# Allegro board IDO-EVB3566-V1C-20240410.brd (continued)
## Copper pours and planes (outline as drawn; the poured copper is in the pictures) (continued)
VBAT_WL_1T1R on TOP: 83.57,48.18 83.57,46.23 83.69,46.1 84.2,46.1 84.2,47.62 84.84,48.26 86.61,48.26 87.99,49.63 88.21,49.63 88.37,49.78 88.37,50.47 88.32,50.52 87.63,50.52 86.26,49.15 84.33,49.15 83.86,48.68 83.86,48.48
VCC2V8_DVP on BOTTOM: 53.31,7.37 52.12,7.37 51.97,7.21 51.97,4.65 51.99,4.62 51.99,3.51 52.7,2.79 54.99,2.79 55.12,2.92 55.12,3.81 54.99,3.94 54.23,3.94 53.37,4.8 53.37,7.32
VCC2V8_DVP on BOTTOM: 78.87,4.32 78.23,4.32 77.98,4.06 77.22,4.06 76.71,3.56 76.71,2.16 76.83,2.03 78.26,2.03 78.36,2.13 78.36,3 78.44,3.07 78.89,3.07 78.99,3.17 78.99,4.19
VCC2V8_DVP on L3_S2: 70.46,4.22 71.96,5.71 75.06,5.71 75.44,5.33 75.44,2.54 75.69,2.29 77.6,2.29 77.98,2.67 77.98,4.45 75.56,6.86 69.34,6.86 69.02,6.54 67.3,6.54 66.42,5.66 55.45,5.66 53.98,4.19 53.98,3.56 54.1,3.43 56.26,3.43 57.66,4.83 60.58,4.83 61.19,4.22
VCC3V3_SYS on TOP: 41.1,20.83 41.1,19.71 42.21,18.59 45.19,18.59 45.67,19.08 47.5,19.08 47.57,19 48.41,19 49.43,20.02 49.43,32.49 49.5,32.56 61.77,32.56 61.93,32.72 61.93,33.25 61.47,33.71 49.81,33.71 49.45,33.35 49.17,33.35 48.67,32.84 48.67,32.54 48.01,31.88 48.01,20.73 47.35,20.07 42.49,20.07 42.37,20.19 42.37,20.95 42.24,21.08 41.35,21.08
VCC3V3_SYS on TOP: 14.05,16.41 16.92,16.41 17.14,16.64 17.14,17.5 17.37,17.73 18.01,17.73 18.54,18.26 19.23,18.26 19.66,18.69 19.66,20.45 19.46,20.65 16.81,20.65 16.51,20.35 14,20.35 13.84,20.19 13.84,16.61
VCC3V3_SYS on TOP: 86.82,47.73 88.24,47.73 88.37,47.85 88.37,48.97 88.34,49 87.53,49 87.53,48.72 87.1,48.29 87,48.29 86.82,48.11
VCC3V3_SYS on BOTTOM: 68.55,19.86 68.38,20.04 68.38,20.32 68.35,20.35 63.98,20.35 63.73,20.6 63.73,32.44 63.65,32.51 61.21,32.51 60.93,32.79 60.93,33.38 61.26,33.71 61.48,33.71 61.59,33.59 64.55,33.59 64.85,33.3 64.85,21.64 65.41,21.08 67.34,21.08 67.69,21.44 67.69,22.12 67.74,22.17 69.27,22.17 69.29,22.15 69.29,21.79 70.92,21.79 77.42,28.3 77.83,28.3 78.08,28.55 78.08,28.96 78.44,29.31 78.44,29.54 79.17,30.28 79.17,31.04 80.54,32.41 81.2,32.41 81.61,32 81.61,31.72 80.64,30.76 80.64,29.03 78.91,27.29 78.57,27.29 78.33,27.05 78.33,26.72 71.96,20.35 69.01,20.35 69.01,20.09 68.78,19.86
VCC3V3_SYS on BOTTOM: 45.06,7.7 44.75,7.39 44.75,6.78 44.7,6.73 43.99,6.73 43.94,6.78 43.94,9.17 43.99,9.22 44.68,9.22 45.06,8.84
VCC3V3_SYS on BOTTOM: 86.56,47.85 86.56,40.54 86.77,40.34 87.55,40.34 87.73,40.51 87.73,47.5 87.96,47.73 87.96,48.16 87.78,48.34 87.05,48.34
VCC3V3_SYS on L3_S2: 80.39,32.18 80.39,32.16 80.26,32.03 80.26,31.83 80.75,31.34 88.34,31.34 89.09,32.09 89.89,32.09 90.06,32.26 90.7,32.26 92.2,33.76 92.2,36.6 87.86,40.94 86.69,40.94 86.56,40.82 86.56,40.46 91.16,35.86 91.16,34.37 91.03,34.24 91.03,34.06 90.61,33.64 90.44,33.64 89.97,33.17 88.57,33.17 87.78,32.38 80.59,32.38
VCC3V3_SYS on L3_S2: 21.23,13.41 20.87,13.78 19.37,13.78 16.36,16.79 16.36,17.48 16.28,17.55 16.28,18.75 16.41,18.87 17.42,18.87 17.58,18.72 17.58,17.09 19.51,15.16 20.88,15.16 21.49,14.55 25.76,14.55 26.64,15.44 28.45,15.44 28.83,15.06 34.26,15.06 34.52,14.81 36.42,14.81 36.68,15.06 36.75,15.06 39.93,18.24 39.93,19.84 41.35,21.26 42.19,21.26 42.34,21.11 42.34,20.52 42.16,20.35 41.88,20.35 41.05,19.51 41.05,17.78 37.2,13.93 36.08,13.93 35.69,13.54 26.49,13.54 26.37,13.41
VCC5V0_USB_FE_D1 on BOTTOM: 90.42,18.54 93.85,18.54 95.38,20.07 97.28,20.07 97.41,20.19 97.41,21.34 97.28,21.46 94.61,21.46 93.09,19.94 90.3,19.94 90.17,19.81 90.17,18.8
VCC5V0_USB_FE_D1 on L3_S2: 103,23.75 100.08,23.75 98.17,21.84 96.65,21.84 96.39,21.59 96.39,19.94 96.65,19.68 98.93,19.68 100.97,21.72 103,21.72 103.12,21.84 103.12,23.62
VCC5V0_USB_FE_D2 on BOTTOM: 97.41,34.54 95.89,34.54 95,35.43 91.87,35.43 90.96,34.52 90.96,34.06 90.3,33.4 90.3,32.38 90.35,32.33 91.77,32.33 91.82,32.38 91.82,32.77 91.95,32.89 93.47,32.89 93.98,32.38 97.41,32.38 97.54,32.51 97.54,34.42
VCC5V0_USB_FE_D3 on BOTTOM: 90.5,24.38 95.89,24.38 96.27,24 97.26,24 97.54,23.72 97.54,22.33 96.88,21.67 95.45,21.67 93.8,23.32 92.02,23.32 91.82,23.52 90.6,23.52 90.4,23.72 90.4,24.28
VCC5V0_USB_FE_D4 on BOTTOM: 94.61,15.24 92.13,15.24 91.59,14.71 90.6,14.71 90.3,14.4 90.3,13.72 90.42,13.59 95,13.59 95.25,13.84 95.25,14.61
VCC5V0_USB_FE_D4 on L3_S2: 95.63,15.37 94.36,15.37 94.11,15.11 94.11,14.1 94.82,13.39 94.82,10.85 95.63,10.03 101.68,10.03 103.23,11.58 103.23,12.85 102.84,13.23 101.6,13.23 101.37,13 101.37,12.73 100.08,11.43 96.14,11.43 95.94,11.63 95.94,15.06
VCC5V0_USB_HOST1 on TOP: 46.61,57.4 45.97,57.4 45.85,57.53 45.85,60.07 46.23,60.45 47.5,60.45 47.75,60.2 47.75,59.69 47.5,59.44 46.99,59.44 46.74,59.18 46.74,57.53
VCC5V0_USB_HOST1 on BOTTOM: 56.01,61.59 46.35,61.59 46.1,61.34 46.1,59.69 46.35,59.44 52.93,59.44 53.14,59.64 53.52,59.64 53.72,59.44 55.75,59.44 56.26,59.94 56.26,61.34
VCC5V0_USB_HOST2 on BOTTOM: 90.55,28.32 94.74,28.32 95.12,27.94 95.12,26.92 94.87,26.67 94.23,26.67 93.73,27.18 92.2,27.18 91.82,27.56 90.55,27.56 90.42,27.69 90.42,28.19
VCC5V0_USB_HOST2 on L3_S2: 100.84,34.42 98.81,32.38 96.6,32.38 93.98,29.77 93.98,26.92 94.49,26.42 95.38,26.42 96.52,27.56 97.87,27.56 103.15,32.84 103.15,34.34 103.07,34.42
VCC5V0_USB_OTG on TOP: 64.39,55.88 64.52,55.75 66.42,55.75 66.55,55.88 66.55,60.2 66.42,60.33 64.64,60.33 64.39,60.07
VCC5V0_USB_OTG on TOP: 72.26,56.9 74.3,56.9 74.42,57.02 74.42,58.93 74.3,59.05 72.26,59.05 72.14,58.93 72.14,57.02
VCC5V0_USB_OTG on BOTTOM: 74.68,57.02 74.68,59.05 74.17,59.56 67.69,59.56 66.93,60.33 65.41,60.33 65.28,60.2 65.28,56.64 66.04,55.88 72.14,55.88 73.15,56.9 74.55,56.9
VCC5V_SYS on TOP: 53.72,43.94 53.72,36.2 54.1,35.81 58.17,35.81 58.78,36.42 58.78,44.07 58.65,44.2 53.98,44.2
VCC5V_SYS on TOP: 73.91,48.64 71.53,48.64 71.37,48.79 71.37,50.42 71.53,50.57 73.86,50.57 74.04,50.39 74.04,48.77
VCC5V_SYS on TOP: 11.76,28.4 19.99,28.4 20.07,28.32 20.07,25.4 19.56,24.89 15.88,24.89 15.75,25.02 15.75,26.04 15.11,26.67 11.68,26.67 11.56,26.8 11.56,28.19
VCC5V_SYS on BOTTOM: 72.8,48.13 73.36,48.13 73.38,48.16 73.38,48.9 74.14,49.66 74.14,54.69 74.13,54.7 73.19,54.7 72.57,54.08 72.57,54.03 71.37,52.83 71.37,51.94 71.2,51.77 71.2,49.15 71.53,48.82 72.59,48.82 72.77,48.64 72.77,48.16
VCC5V_SYS on L3_S2: 62.81,46.61 55.75,46.61 55.24,46.1 55.24,43.56 55.37,43.43 60.33,43.43 60.77,43.88 67.37,43.88 67.56,44.07 70.74,44.07 73.41,46.74 73.41,49.91 72.26,51.05 67.26,51.05
VCC5V_SYS on L3_S2: 18.44,25.27 23.11,25.27 26.16,28.32 30.73,28.32 35.31,32.89 63.37,32.89 64.26,33.78 64.26,35.56 64.11,35.71 62.94,35.71 61.57,37.08 45.62,37.08 45.44,36.91 33.6,36.91 29.72,33.02 23.37,33.02 17.75,27.41 17.75,25.96
VCC-AMP on TOP: 85.98,30.1 82.55,30.1 82.42,29.97 82.42,26.29 82.55,26.16 85.9,26.16 86.11,26.37 86.11,26.67 86.03,26.75 84.28,26.75 84.23,26.8 84.23,28.85 84.12,28.96 84.12,29.36 84.23,29.46 85.98,29.46 86.11,29.59 86.11,29.97
VCC-AMP on BOTTOM: 83.79,31.5 82.93,31.5 82.68,31.24 82.68,26.21 82.8,26.09 82.8,25.37 82.91,25.27 83.62,25.27 84.28,25.93 84.28,28.83 84.12,28.98 84.12,30.12 83.87,30.38 83.87,31.42
VCC_3V3_HUB on TOP: 84.73,16.23 84.66,16.15 84.66,15.27 84.71,15.21 85.19,15.21 85.78,14.63 88.37,14.63 88.39,14.66 88.39,15.44 88.37,15.47 87.38,15.47 86.61,16.23
VCC_3V3_HUB on TOP: 81.97,21.29 81.97,20.45 81.84,20.32 81.13,20.32 80.72,20.73 80.72,21.16 80.87,21.31 81.94,21.31
VCC_3V3_HUB on TOP: 88.01,20.27 89.05,20.27 89.13,20.19 89.13,18.77 88.93,18.57 88.01,18.57 87.96,18.62 87.96,20.22
VCC_3V3_HUB on TOP: 85.29,19.81 85.47,19.63 86.33,19.63 86.33,19.71 87.6,20.98 87.6,22.28 87.4,22.48 87.4,23.29 87.25,23.44 82.85,23.44 82.83,23.42 82.83,22.89 82.85,22.86 86.16,22.86 86.23,22.78 86.23,21.77 85.29,20.83
VCC_3V3_HUB on BOTTOM: 87.33,20.88 85.93,20.88 84.58,22.23 80.14,22.23 79.5,21.59 79.5,18.92 78.54,17.96 77.19,17.96 77.06,17.83 77.06,16.99 79.07,14.99 85.85,14.99 85.89,15.02 85.89,16.09 85.78,16.21 85.37,16.21 85.17,16 81.41,16 80.77,16.64 80.77,20.09 80.87,20.19 81.41,20.19 81.94,20.73 84.71,20.73 84.86,20.57 84.86,19.91 84.89,19.89 85.27,19.89 85.65,19.51 89.03,19.51 89.15,19.63 89.15,19.91 89,20.07 88.14,20.07
VCC_5V on TOP: 4.6,48.29 4.6,50.62 1.4,50.62 1.4,48.29
VCC_5V on TOP: 16,38.48 15.49,38.99 11.43,38.99 11.18,38.73 11.18,36.83 11.43,36.58 18.41,36.58 18.8,36.2 20.7,36.2 20.83,36.32 20.83,37.87 20.22,38.48
VCC_5V on TOP: 74.93,56.9 77.47,56.9 77.6,57.02 77.6,59.18 77.34,59.44 75.06,59.44 74.8,59.18 74.8,57.02
VCC_5V on TOP: 5.31,11.66 5.31,14.27 3.51,16.08 1.85,16.08 1.68,16.26 1.68,17.7 2.13,18.16 5.77,18.16 6.38,17.55 6.38,11.84 8.18,10.03 9.35,10.03 9.73,9.65 11.79,9.65 11.84,9.6 11.84,8.97 11.19,8.32 8.65,8.32
VCC_5V on TOP: 77.42,21.26 77.57,21.11 77.98,21.11 78.16,21.29 78.16,21.44 78.31,21.59 78.31,21.97 78.33,22 78.46,22 78.56,22.1 79.1,22.1 79.12,22.12 79.12,22.73 79.04,22.81 78.05,22.81 77.42,22.17
VCC_5V on BOTTOM: 57.78,61.85 60.45,61.85 60.58,61.72 60.58,58.8 60.33,58.55 57.78,58.55 57.53,58.8 57.53,61.59
VCC_5V on BOTTOM: 82.17,26.16 79.86,26.16 79.76,26.06 79.76,24.59 80.77,23.57 82.25,23.57 82.42,23.75 82.42,25.15 82.22,25.35 82.22,26.11
VCC_5V on BOTTOM: 86.11,14.94 86.11,16.26 85.98,16.38 85.98,19.18 86.11,19.3 88.9,19.3 89.03,19.18 89.03,17.78 88.9,17.65 87.63,17.65 87.5,17.53 87.5,16.76 87.76,16.51 88.77,16.51 89.03,16.26 89.03,12.95 88.9,12.83 86.92,12.83 86.87,12.88 86.87,13.49 85.95,14.4 85.95,14.78
VCC_5V on BOTTOM: 88.98,33.02 86.89,33.02 85.88,32 85.88,23.39 86.06,23.22 88.9,23.22 89.05,23.37 89.05,25.04 88.68,25.41 87.69,25.41 87.66,25.45 87.66,26.97 87.81,27.13 89.1,27.13 89.18,27.2 89.18,28.4 89,28.57 87.73,28.57 87.6,28.7 87.6,29.24 87.76,29.39 87.76,31.37 88.01,31.62 88.98,31.62 89.08,31.72 89.08,32.92
VCC_5V on BOTTOM: 44.68,3.25 43.46,3.25 42.57,2.36 39.93,2.36 39.88,2.41 39.88,2.79 39.75,2.92 37.72,2.92 37.21,2.41 34.67,2.41 34.54,2.29 16.26,2.29 13.72,4.83 13.46,4.83 9.91,8.38 9.91,9.65 9.65,9.91 8.38,9.91 8.26,9.78 8.26,6.63 13.74,1.14 45.47,1.14 45.72,1.4 45.72,3.76 45.64,3.84 44.96,3.84 44.88,3.76 44.88,3.45
VCC_5V on L3_S2: outline of 112 points within 1.23,11.84 96.01,65.53
VCC_12V on TOP: 16.43,42.21 16.38,42.16 15.75,42.16 15.57,42.34 13.36,42.34 13.34,42.37 13.34,42.42 12.06,43.69 12.06,51.59 12.61,52.13 16.12,52.13 16.43,51.82 16.43,48.31 15.39,47.27 15.39,43.87 15.47,43.79 15.93,43.79 16,43.71 16,42.82 16.03,42.8 16.13,42.8 16.43,42.49
VCC_12V on TOP: 27.18,7.49 25.53,7.49 25.4,7.37 25.4,5.84 24.77,5.21 24.77,3.94 24.89,3.81 27.69,3.81 27.81,3.94 27.81,5.33 27.3,5.84 27.3,7.37
VCC_12V on TOP: 16.43,34.11 15.88,34.67 11.56,34.67 11.3,34.42 11.3,32.77 11.56,32.51 12.32,32.51 12.95,33.15 14.35,33.15 15.88,31.62 16.71,31.62 16.74,31.65 16.74,32.69 17.27,33.22 17.27,33.76 17.25,33.78 16.48,33.78 16.43,33.83
VCC_12V on TOP: 73.66,7.39 72.44,7.39 72.39,7.34 72.39,4.78 72.64,4.52 73.53,4.52 73.71,4.7 73.71,5.61 73.69,5.64 73.69,7.37
VCC_12V on BOTTOM: 75.44,5.97 70.36,5.97 70.1,5.71 70.1,4.19 70.23,4.06 75.31,4.06 75.56,4.32 75.56,5.84
VCC_12V on BOTTOM: 15.62,52.32 15.62,47.24 15.24,46.86 11.3,46.86 10.16,48.01 10.16,52.22 10.64,52.7 15.24,52.7
VCC_12V on BOTTOM: 23.88,3.81 28.57,3.81 28.73,3.96 28.73,5.69 28.7,5.71 24.18,5.71 23.75,5.28 23.75,3.94
VCC_12V on L3_S2: 8.13,6.35 8.13,2.41 9.4,1.14 74.55,1.14 75.06,1.65 75.06,5.33 74.8,5.59 72.11,5.59 70.56,4.04 61.19,4.04 59.94,2.79 58.17,2.79 57.66,3.3 30.61,3.3 29.91,4 29.91,4.89 29.34,5.46 25.91,5.46 24,3.56 16.64,3.56 14.86,5.33 12.65,5.33 8.99,8.99 8.99,11.1 8.5,11.6 6.77,11.6 6.27,12.09 6.27,20.6 6.81,21.13 6.81,24.74 5.23,26.31 5.23,32.36 5.19,32.4 5.51,32.72 12.57,32.72 12.57,34.29 11.93,34.94 5.73,34.94 5.21,35.46 5.21,40.01 5.56,40.36 6.2,40.36 13.18,47.35 15.37,47.35 15.88,47.85 15.88,48.9 14.58,50.19 11.48,50.19 1.63,40.34 1.63,12.85
VCC_DCIN on BOTTOM: 7.11,65.28 3.05,65.28 1.63,63.86 1.63,59.59 2.67,58.55 6.73,58.55 10.29,54.99 14.61,54.99 14.69,55.08 14.69,57.16 12.57,59.28 10.06,59.28 9.27,60.07 9.27,62.36 7.37,64.26 7.37,65.02
VCC_LEDA_TX1 on TOP: 54.74,7.34 53.92,7.34 53.85,7.26 53.85,5.84 53.47,5.46 53.47,4.7 53.72,4.45 54.48,4.45 54.61,4.57 54.61,5.54 54.79,5.71 54.79,7.29
VCC_LEDA_TX1 on BOTTOM: 31.39,3.53 31.5,3.43 31.5,2.79 31.75,2.54 33.4,2.54 33.53,2.67 33.53,4.7 32.64,5.59 29.08,5.59 28.96,5.46 28.96,3.81 29.24,3.53
VCC_LEDA_TX1 on L3_S2: 32.21,4.62 31.17,5.66 30.43,5.66 30.23,5.46 30.23,4.19 31.01,3.4 45.09,3.4 47.62,5.94 52.35,5.94 53.85,4.45 54.36,4.45 54.61,4.7 54.61,6.22 53.49,7.34 47.47,7.34 44.75,4.62
VCC_LEDK_TX1 on TOP: 50.8,5.97 49.91,5.97 49.91,8.05 49.63,8.33 48.67,8.33 47.8,7.47 47.42,7.47 47.24,7.65 47.24,7.87 48.34,8.97 50.5,8.97 50.8,8.66
VCCIO5_IN on TOP: 24.26,16.64 22.61,16.64 22.48,16.51 22.48,14.86 22.61,14.73 24.26,14.73 24.38,14.86 24.38,16.51
VCCIO5_IN on BOTTOM: 22.61,14.73 22.99,14.73 23.06,14.81 23.06,15.29 23.14,15.37 23.15,15.35 24.63,15.35 24.69,15.42 24.69,16 24.59,16.1 22.53,16.1 22.43,16 22.43,14.91
VDD_3V3 on TOP: 15.37,14.99 15.24,14.86 15.24,12.32 15.06,12.14 13,12.14 12.73,11.86 12.27,11.86 12.19,11.79 12.19,10.69 12.24,10.64 12.52,10.64 12.67,10.79 16.69,10.79 16.76,10.87 16.76,13.18 16.38,13.56 16.38,14.91 16.31,14.99
VDD_3V3 on TOP: 89.46,21.51 89.15,21.51 88.16,22.5 88.16,23.29 88.19,23.32 88.93,23.32 89.69,22.56 89.69,21.74
VDD_3V3 on TOP: 19.2,7.39 18.44,7.39 18.34,7.29 18.34,5.87 18.06,5.59 17.3,5.59 17.28,5.58 16.5,5.58 16.38,5.46 16.38,3.89 16.54,3.73 18.85,3.73 19.3,4.19 19.3,4.83 19.25,4.88 19.25,7.34
VDD_3V3 on TOP: 90.93,5.97 91.67,5.97 91.69,5.99 91.69,7.49 91.77,7.57 93.5,7.57 93.73,7.8 93.73,8.92 93.64,9 93.62,8.99 89.59,8.99 89.56,8.97 89.56,8.28 89.89,7.95 90.45,7.95 90.91,7.49 90.91,5.99
VDD_3V3 on TOP: 36.17,7.39 35.43,7.39 35.36,7.32 35.36,6.02 35.18,5.84 34.52,5.84 34.42,5.74 34.42,4.57 34.54,4.45 36.04,4.45 36.17,4.57 36.17,5.61 36.25,5.69 36.25,7.32
VDD_3V3 on BOTTOM: 17.88,32.28 17.88,32.97 17.73,33.12 16.76,33.12 16.74,33.15 16.74,33.96 16.71,33.99 16.13,33.99 15.75,33.6 15.75,32.56 15.72,32.54 14.17,32.54 14.12,32.49 14.12,32.08 14.15,32.05 16.15,32.05 16.33,32.23 17.83,32.23
VDD_3V3 on BOTTOM: 14.1,25.53 15.88,25.53 16,25.65 16.64,25.65 16.69,25.6 16.69,25.07 16.64,25.02 16.64,24.38 16.51,24.26 15.75,24.26 15.49,24 14.1,24 13.97,24.13 13.97,25.4
VDD_3V3 on BOTTOM: 78.99,5.97 78.87,5.84 78.11,5.84 77.98,5.97 77.98,6.99 77.72,7.24 77.22,7.24 77.09,7.37 77.09,7.87 77.22,8 77.47,8 78.61,9.14 93.6,9.14 93.98,8.76 93.98,6.99 93.73,6.73 91.06,6.73 90.55,7.24 89.61,7.24 89.61,8.05 89.51,8.15 88.75,8.15 88.65,8.05 88.65,5.97 88.52,5.84 87.88,5.84 87.76,5.97 87.76,6.35 87.5,6.6 86.36,6.6 85.85,7.11 84.73,7.11 84.73,8.05 84.71,8.08 83.92,8.08 83.85,8 83.85,7.09 83.74,7.09 83.74,5.89 83.64,5.79 83.13,5.79 82.94,5.98 82.94,7.1 81.79,8.26 79.12,8.26 79.12,7.16 78.99,7.04
VDD_3V3 on BOTTOM: 19.05,3.56 16.51,3.56 16.38,3.68 16.38,5.21 16.51,5.33 19.05,5.33 19.18,5.21 19.18,3.68
VDD_3V3 on BOTTOM: 36.17,5.61 35.08,5.61 34.92,5.46 34.92,4.7 35.18,4.45 36.07,4.45 36.2,4.57 36.2,5.59
VDD_3V3 on L3_S2: outline of 103 points within 9.32,3.81 94.61,33.15
VDD_USB_5V on TOP: 80.44,20.62 80.52,20.7 80.52,21.29 80.63,21.4 80.64,21.4 80.64,21.41 80.75,21.51 82.04,21.51 82.17,21.39 82.17,20.4 82.22,20.35 82.4,20.35 82.47,20.42 82.47,23.34 82.32,23.5 81.48,23.5 81.36,23.37 81.36,22.78 80.92,22.35 79.91,22.35 79.5,21.95 79.5,21.64 79.22,21.36 78.33,21.36 78.28,21.31 78.28,20.65 78.31,20.62
(no net) on TOP: 100.2,69.6 103.76,69.6 104.39,69.34 104.65,68.71 104.65,1.27 104.39,0.64 103.76,0.38 1.27,0.38 0.64,0.64 0.38,1.27 0.38,68.71 0.64,69.34 1.27,69.6 13.97,69.6 14.22,69.34 14.22,56.39 14.33,56.29 14.33,56.26 17.45,53.14 31.83,53.14 34.72,56.03 34.72,67.92 34.67,67.97 34.67,69.34 34.92,69.6 95.89,69.6 95.89,68.33 100.2,68.33 ; 83 cut-outs
(no net) on BOTTOM: 14.2,69.6 14.2,57.94 18.03,54.1 18.03,49.1 18.24,48.9 18.24,45.21 20.35,43.1 29.9,43.1 34.62,47.83 34.62,69.6 95.89,69.6 95.89,68.33 100.2,68.33 100.2,69.6 103.76,69.6 104.39,69.34 104.65,68.71 104.65,1.27 104.39,0.64 103.76,0.38 1.27,0.38 0.64,0.64 0.38,1.27 0.38,68.71 0.64,69.34 1.27,69.6 ; 89 cut-outs
N69227900 on TOP: 15.88,23.37 16.76,23.37 16.89,23.24 16.89,21.08 16.74,20.93 14.3,20.93 14.22,21.01 14.22,21.97 14.33,22.07 15.7,22.07 15.75,22.12 15.75,23.24
N69864462 on TOP: 82.3,36.07 80.62,36.07 80.25,35.7 80.25,34.53 80.01,34.29 77.85,34.29 77.85,33.4 77.98,33.27 82.42,33.27 82.55,33.4 82.55,34.67 82.42,34.8 82.42,35.94
N69864477 on TOP: 81.53,37.72 79.81,37.72 79.17,37.08 78.54,37.08 77.83,36.37 77.83,35.61 77.88,35.56 79.88,35.56 79.98,35.66 79.98,35.94 80.06,36.02 80.06,36.78 80.19,36.91 81.56,36.91 81.66,37.01 81.66,37.59
N69912226 on BOTTOM: 36.58,4.32 37.34,5.08 40.31,5.08 40.56,4.83 40.56,3.51 40.77,3.3 42.11,3.3 42.16,3.25 42.16,2.54 42.11,2.49 40.06,2.49 40.01,2.54 40.01,2.87 39.8,3.07 39.8,4.11 39.75,4.17 37.54,4.17 37.34,3.96 37.34,2.67 37.21,2.54 35.18,2.54 35.05,2.67 35.05,4.19 35.18,4.32
N69966774 on TOP: 16.76,31.5 14.1,31.5 13.34,32.26 12.19,32.26 11.56,31.62 11.56,29.97 11.76,29.77 15.8,29.77 16,29.97 16,30.99 16.08,31.06 16.79,31.06 16.81,31.09 16.81,31.45
N70572735 on TOP: 8.38,12.83 10.03,12.83 10.54,13.34 11.76,13.34 11.94,13.16 11.94,10.16 11.76,9.98 9.14,9.98 8.26,10.87 8.26,12.7
N70591050 on TOP: 16.38,42.04 15.7,42.04 15.52,42.21 11.35,42.21 11.05,41.91 11.05,40.51 11.18,40.39 15.49,40.39 15.62,40.51 15.62,41.53 15.75,41.66 16.38,41.66 16.51,41.78 16.51,41.91

Small or netless copper shapes (teardrops, artwork), in the pictures only: 18 on TOP, 11 on BOTTOM, 1 on L3_S2

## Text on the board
Ref Des/Silkscreen Bottom: GND | RX9 | TX9 | RX7 | RX5 | TX5 | TX7 | RX0 | TX0 | 5V | RX | TX | SARADC_1 | SARADC_2 | VCC_3V3 | RSESTN | PWRON | I2C3_SDA | I2C3_SCL | PWM7_IR | PWM6 | SPI3_MOSI | SPI3_MISO | SPI3_CLK | SPI3_CS0 | VCC | VOLP | VORN | VORP | VOLN | DP | DM | MIC | J43 | J41 | J40 | J42 | J31 | J22 | J46 | MIPI-CSI | J10 | REC | SW4 | J36 | J37 | J25 | J39 | J13 | J38
Ref Des/Silkscreen Top: GND | MIC_IN | J46 | TX | RX | J31 | J42 | J40 | J43 | J41 | SDA | SCL | INT | RST | VCC | VBAT | J36 | J25 | J37 | J39 | J13 | J38 | J1 | J22 | J5 | J12 | J16 | J15 | J8 | J9 | J7 | J6 | LED3 | MIC | J3 | RTC | J11 | eDP | IDO-EVB3566-V1C | MIPI-DSI | TP | LVDS
User.16: FIGURE | SIZE | 11.811 | 31.496 | 32.0 | 39.37 | 145.669 | 23.618 | 51.181 | 55.0 | 90.551 | 66.929x35.429 | 78.74x23.622 | 78.74x31.5 | 86.614x15.748 | 106.299x35.429 | DRILL CHART: TOP to BOTTOM | ALL UNITS ARE IN MILS | PLATED | NON-PLATED | QTY | 36 | 1211 | 44 | 10 | 2 | 4 | 1 | 3
